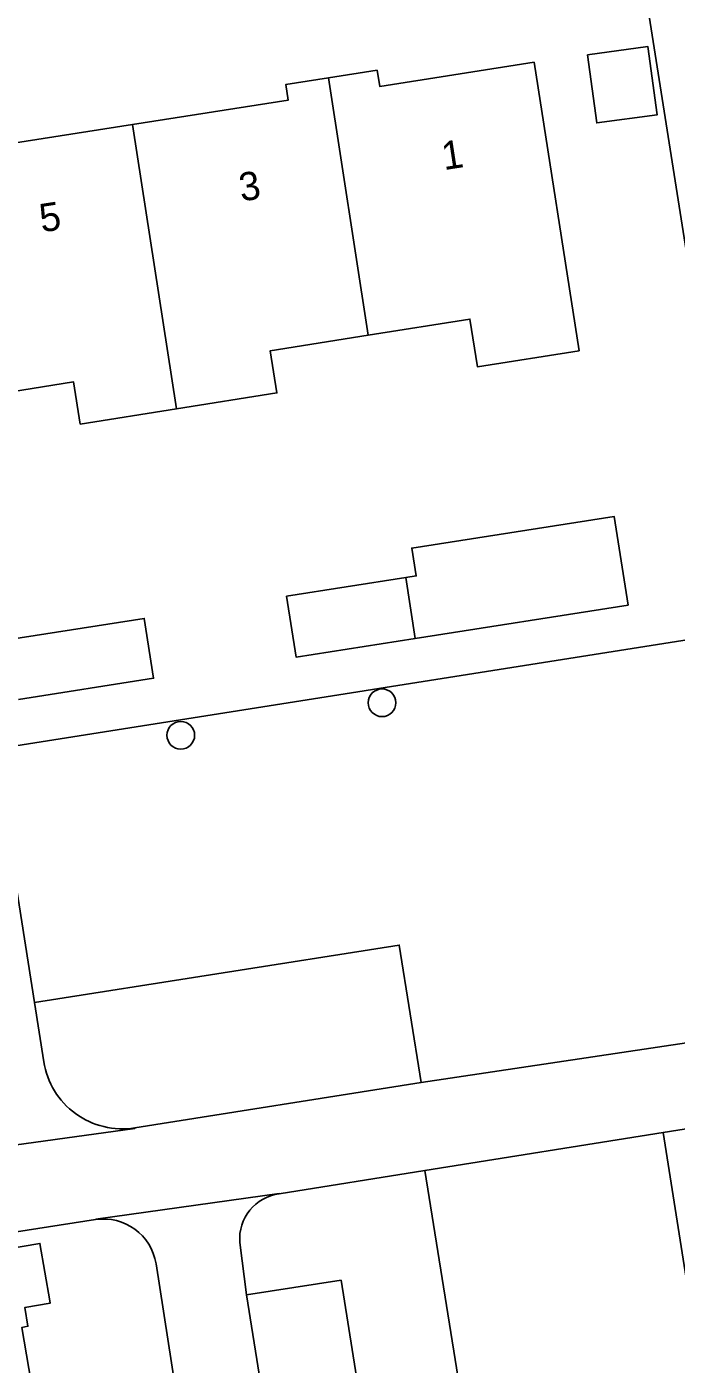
# Model space of a CAD drawing. Extents: x 160077 to 160945, y 386481 to 387498.
# Drawn here: x 160597.37 to 160620.3, y 387146.34 to 387193.58 of the extents above; entities that cross this region are included whole.
import ezdxf

# ---------------------------------------------------------------- set-up
doc = ezdxf.new("R2010")
doc.units = 0
for name, color, linetype in [('IMGEO_Boom', 7, 'Continuous'), ('IMGEO_Groenvoorziening', 7, 'Continuous'), ('IMGEO_Pand', 7, 'Continuous'), ('IMGEO_Pand_nummerreeks', 7, 'Continuous'), ('IMGEO_Rijbaan_lokaal_open', 7, 'Continuous'), ('IMGEO_Voetpad_open', 7, 'Continuous')]:
    doc.layers.add(name, color=color, linetype=linetype)

msp = doc.modelspace()

# ---------------------------------------------------------------- linework, layer by layer
at = {"layer": 'IMGEO_Boom'}
for centre in [(160609.917, 387169.701), (160602.81, 387168.554)]:
    msp.add_circle(centre, 0.489, dxfattribs=at)
at = {"layer": 'IMGEO_Groenvoorziening'}
for points in [[(160595.851, 387168.006), (160622.773, 387172.259)], [(160597.647, 387159.11), (160610.525, 387161.141), (160611.294, 387156.291)], [(160627.085, 387108.61), (160619.835, 387154.524)], [(160612.64, 387123.04), (160616.166, 387123.612), (160611.425, 387153.179)]]:
    msp.add_lwpolyline(points, dxfattribs=at)
at = {"layer": 'IMGEO_Pand'}
for points in [[(160617.174, 387192.591), (160619.305, 387192.877), (160619.629, 387190.468), (160617.498, 387190.181), (160617.174, 387192.591)], [(160608.023, 387191.772), (160609.743, 387192.041), (160609.832, 387191.472), (160615.283, 387192.323), (160616.874, 387182.134), (160613.28, 387181.572), (160613.018, 387183.252), (160609.43, 387182.683)], [(160601.107, 387190.127), (160606.599, 387190.985), (160606.513, 387191.536), (160608.023, 387191.772)], [(160608.023, 387191.772), (160609.43, 387182.683)], [(160594.032, 387189.525), (160595.689, 387189.784), (160595.765, 387189.293), (160601.107, 387190.127)], [(160602.663, 387180.081), (160601.107, 387190.127)], [(160609.43, 387182.683), (160605.97, 387182.135), (160606.206, 387180.643), (160602.663, 387180.081)], [(160602.663, 387180.081), (160599.262, 387179.542), (160599.025, 387181.033), (160595.436, 387180.464)], [(160610.756, 387174.123), (160611.126, 387174.181), (160610.965, 387175.164), (160618.109, 387176.284), (160618.601, 387173.151), (160611.089, 387171.973)], [(160611.089, 387171.973), (160606.88, 387171.313), (160606.543, 387173.462), (160610.756, 387174.123)], [(160611.089, 387171.973), (160610.756, 387174.123)], [(160596.757, 387171.935), (160601.518, 387172.681), (160601.849, 387170.568), (160597.084, 387169.821)], [(160589.356, 387138.611), (160588.739, 387142.241), (160584.795, 387141.57), (160584.139, 387145.429), (160583.82, 387147.304), (160592.221, 387148.726), (160592.068, 387149.63), (160597.838, 387150.607), (160598.182, 387148.576), (160598.197, 387148.49), (160597.3, 387148.338), (160597.413, 387147.677), (160597.202, 387147.641), (160597.776, 387144.255), (160600.083, 387144.098), (160600.707, 387140.417)]]:
    msp.add_lwpolyline(points, dxfattribs=at)
at = {"layer": 'IMGEO_Rijbaan_lokaal_open'}
for points in [[(160612.64, 387123.04), (160608.471, 387149.302), (160605.133, 387148.791)], [(160605.89, 387144), (160605.133, 387148.791)]]:
    msp.add_lwpolyline(points, dxfattribs=at)
at = {"layer": 'IMGEO_Voetpad_open'}
for points in [[(160619.1, 387195.535), (160622.773, 387172.259)], [(160597.647, 387159.11), (160596.754, 387164.815)], [(160597.974, 387157.024), (160597.647, 387159.11)], [(160622.849, 387158.043), (160621.92, 387157.879), (160611.294, 387156.291)], [(160611.294, 387156.291), (160601.186, 387154.687)], [(160619.835, 387154.524), (160622.363, 387154.928), (160623.51, 387155.098)], [(160601.186, 387154.687), (160601.189, 387154.665), (160595.546, 387153.889)], [(160611.425, 387153.179), (160619.835, 387154.524)], [(160606.284, 387152.356), (160611.425, 387153.179)], [(160606.284, 387152.356), (160606.281, 387152.367), (160599.805, 387151.456), (160599.798, 387151.446)], [(160577.918, 387148.033), (160599.798, 387151.446)], [(160605.133, 387148.791), (160604.895, 387150.64)], [(160601.936, 387149.886), (160610.294, 387095.917)]]:
    msp.add_lwpolyline(points, dxfattribs=at)
for centre, radius, start, end in [((160600.745, 387157.457), 2.805, 188.8816, 279.0404), ((160606.492, 387150.768), 1.602, 97.4489, 184.5749), ((160600.084, 387149.593), 1.875, 8.9783, 98.7887)]:
    msp.add_arc(centre, radius, start, end, dxfattribs=at)

# ---------------------------------------------------------------- texts
at = {"layer": 'IMGEO_Pand_nummerreeks'}
for s, p in [('1', (160612.102, 387188.512)), ('3', (160604.945, 387187.403)), ('5', (160597.9, 387186.312))]:
    msp.add_text(s, height=1, rotation=8.804, dxfattribs=at).set_placement(p)

doc.saveas('drawing.dxf')
